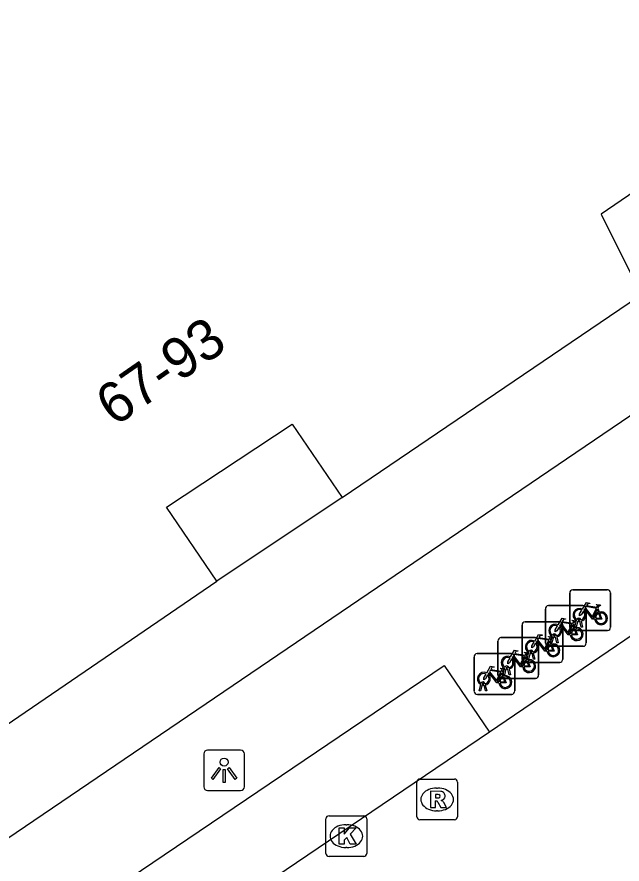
# Model space of a CAD drawing. Extents: x 160037 to 160839, y 385326 to 386441.
# Drawn here: x 160304.54 to 160319.39, y 386009.62 to 386030.43 of the extents above; entities that cross this region are included whole.
import ezdxf

# ---------------------------------------------------------------- set-up
doc = ezdxf.new("R2010")
doc.units = 0
for name, color, linetype in [('IMGEO_Fietsenrek', 7, 'Continuous'), ('IMGEO_Kolk', 7, 'Continuous'), ('IMGEO_Lichtpunt', 7, 'Continuous'), ('IMGEO_Pand', 7, 'Continuous'), ('IMGEO_Pand_nummerreeks', 7, 'Continuous'), ('IMGEO_Rijbaan_lokaal_open', 7, 'Continuous'), ('IMGEO_Rioolput', 7, 'Continuous'), ('IMGEO_Voetpad_open', 7, 'Continuous')]:
    doc.layers.add(name, color=color, linetype=linetype)

msp = doc.modelspace()

# ---------------------------------------------------------------- linework, layer by layer
at = {"layer": 'IMGEO_Fietsenrek'}
for p, q in [((160318.109, 386015.434), (160318.109, 386016.275)), ((160318.109, 386016.275), (160318.109, 386015.434)), ((160318.184, 386016.359), (160319.025, 386016.359)), ((160319.025, 386016.359), (160318.184, 386016.359)), ((160319.109, 386016.284), (160319.109, 386015.443)), ((160319.109, 386015.443), (160319.109, 386016.284)), ((160317.512, 386015.046), (160317.512, 386015.887)), ((160317.512, 386015.887), (160317.512, 386015.046)), ((160317.587, 386015.971), (160318.428, 386015.971)), ((160318.428, 386015.971), (160317.587, 386015.971)), ((160318.512, 386015.896), (160318.512, 386015.055)), ((160318.512, 386015.055), (160318.512, 386015.896)), ((160318.796, 386015.908), (160318.832, 386015.813)), ((160316.938, 386014.649), (160316.938, 386015.49)), ((160316.938, 386015.49), (160316.938, 386014.649)), ((160317.013, 386015.574), (160317.854, 386015.574)), ((160317.854, 386015.574), (160317.013, 386015.574)), ((160317.938, 386015.499), (160317.938, 386014.658)), ((160317.938, 386014.658), (160317.938, 386015.499)), ((160318.199, 386015.52), (160318.235, 386015.425)), ((160318.236, 386015.443), (160318.275, 386015.603)), ((160318.27, 386015.443), (160318.236, 386015.443)), ((160318.305, 386015.591), (160318.27, 386015.443)), ((160318.347, 386015.615), (160318.346, 386015.619)), ((160318.388, 386015.443), (160318.354, 386015.585)), ((160318.378, 386015.626), (160318.379, 386015.619)), ((160318.386, 386015.589), (160318.421, 386015.443)), ((160318.421, 386015.443), (160318.388, 386015.443)), ((160317.75, 386015.227), (160317.749, 386015.231)), ((160317.781, 386015.238), (160317.782, 386015.231)), ((160319.034, 386015.359), (160318.193, 386015.359)), ((160318.193, 386015.359), (160319.034, 386015.359)), ((160316.345, 386014.26), (160316.345, 386015.101)), ((160316.345, 386015.101), (160316.345, 386014.26)), ((160316.42, 386015.185), (160317.261, 386015.185)), ((160317.261, 386015.185), (160316.42, 386015.185)), ((160317.345, 386015.11), (160317.345, 386014.269)), ((160317.345, 386014.269), (160317.345, 386015.11)), ((160317.625, 386015.123), (160317.661, 386015.028)), ((160317.639, 386015.055), (160317.678, 386015.215)), ((160317.673, 386015.055), (160317.639, 386015.055)), ((160317.708, 386015.203), (160317.673, 386015.055)), ((160317.791, 386015.055), (160317.757, 386015.197)), ((160317.789, 386015.201), (160317.824, 386015.055)), ((160317.824, 386015.055), (160317.791, 386015.055)), ((160317.065, 386014.658), (160317.104, 386014.818)), ((160317.134, 386014.806), (160317.099, 386014.658)), ((160317.176, 386014.83), (160317.175, 386014.834)), ((160317.217, 386014.658), (160317.183, 386014.8)), ((160317.207, 386014.841), (160317.208, 386014.834)), ((160317.215, 386014.804), (160317.25, 386014.658)), ((160318.437, 386014.971), (160317.596, 386014.971)), ((160317.596, 386014.971), (160318.437, 386014.971)), ((160315.76, 386013.866), (160315.76, 386014.707)), ((160315.76, 386014.707), (160315.76, 386013.866)), ((160315.835, 386014.791), (160316.676, 386014.791)), ((160316.676, 386014.791), (160315.835, 386014.791)), ((160316.76, 386014.716), (160316.76, 386013.875)), ((160316.76, 386013.875), (160316.76, 386014.716)), ((160317.032, 386014.734), (160317.068, 386014.639)), ((160317.099, 386014.658), (160317.065, 386014.658)), ((160317.25, 386014.658), (160317.217, 386014.658)), ((160316.472, 386014.269), (160316.511, 386014.429)), ((160316.541, 386014.417), (160316.506, 386014.269)), ((160316.583, 386014.441), (160316.582, 386014.445)), ((160316.624, 386014.269), (160316.59, 386014.411)), ((160316.614, 386014.452), (160316.615, 386014.445)), ((160316.622, 386014.415), (160316.657, 386014.269)), ((160317.863, 386014.574), (160317.022, 386014.574)), ((160317.022, 386014.574), (160317.863, 386014.574)), ((160317.27, 386014.185), (160316.429, 386014.185)), ((160316.429, 386014.185), (160317.27, 386014.185)), ((160316.447, 386014.34), (160316.483, 386014.245)), ((160316.506, 386014.269), (160316.472, 386014.269)), ((160316.657, 386014.269), (160316.624, 386014.269)), ((160315.887, 386013.875), (160315.926, 386014.035)), ((160315.956, 386014.023), (160315.921, 386013.875)), ((160315.998, 386014.047), (160315.997, 386014.051)), ((160316.039, 386013.875), (160316.005, 386014.017)), ((160316.029, 386014.058), (160316.03, 386014.051)), ((160316.037, 386014.021), (160316.072, 386013.875)), ((160316.685, 386013.791), (160315.844, 386013.791)), ((160315.844, 386013.791), (160316.685, 386013.791)), ((160315.921, 386013.875), (160315.887, 386013.875)), ((160316.072, 386013.875), (160316.039, 386013.875))]:
    msp.add_line(p, q, dxfattribs=at)
for points in [[(160318.422, 386015.885), (160318.517, 386016.049), (160318.603, 386016.035), (160318.605, 386016.026), (160318.549, 386016.015), (160318.522, 386015.97), (160318.778, 386015.929)], [(160318.443, 386015.833), (160318.391, 386015.743), (160318.351, 386015.718), (160318.352, 386015.765), (160318.407, 386015.859)], [(160318.718, 386015.641), (160318.668, 386015.641), (160318.477, 386015.892), (160318.458, 386015.86)], [(160318.765, 386015.904), (160318.508, 386015.945), (160318.491, 386015.916), (160318.658, 386015.696), (160318.765, 386015.904)], [(160318.813, 386015.806), (160318.783, 386015.883), (160318.674, 386015.665), (160318.717, 386015.665)], [(160318.778, 386015.929), (160318.803, 386015.978), (160318.797, 386015.982), (160318.774, 386015.986), (160318.762, 386015.993), (160318.761, 386015.996), (160318.763, 386016.001), (160318.858, 386015.986), (160318.86, 386015.976), (160318.85, 386015.963), (160318.838, 386015.957), (160318.824, 386015.963), (160318.796, 386015.908)], [(160317.825, 386015.497), (160317.92, 386015.661), (160318.006, 386015.647), (160318.008, 386015.638), (160317.952, 386015.627), (160317.925, 386015.582), (160318.181, 386015.541)], [(160318.747, 386015.665), (160318.867, 386015.664), (160318.823, 386015.778)], [(160318.843, 386015.785), (160318.898, 386015.64), (160318.748, 386015.64)], [(160317.846, 386015.445), (160317.794, 386015.355), (160317.754, 386015.33), (160317.755, 386015.377), (160317.81, 386015.471)], [(160318.121, 386015.253), (160318.071, 386015.253), (160317.88, 386015.504), (160317.861, 386015.472)], [(160318.168, 386015.516), (160317.911, 386015.557), (160317.894, 386015.528), (160318.061, 386015.308), (160318.168, 386015.516)], [(160318.216, 386015.418), (160318.186, 386015.495), (160318.077, 386015.277), (160318.12, 386015.277)], [(160318.181, 386015.541), (160318.206, 386015.59), (160318.2, 386015.594), (160318.177, 386015.598), (160318.165, 386015.605), (160318.164, 386015.608), (160318.166, 386015.613), (160318.261, 386015.598), (160318.263, 386015.588), (160318.253, 386015.575), (160318.241, 386015.569), (160318.227, 386015.575), (160318.199, 386015.52)], [(160317.251, 386015.1), (160317.346, 386015.264), (160317.432, 386015.25), (160317.434, 386015.241), (160317.378, 386015.23), (160317.351, 386015.185), (160317.607, 386015.144)], [(160318.15, 386015.277), (160318.27, 386015.276), (160318.226, 386015.39)], [(160318.246, 386015.397), (160318.301, 386015.252), (160318.151, 386015.252)], [(160317.272, 386015.048), (160317.22, 386014.958), (160317.18, 386014.933), (160317.181, 386014.98), (160317.236, 386015.074)], [(160317.547, 386014.856), (160317.497, 386014.856), (160317.306, 386015.107), (160317.287, 386015.075)], [(160317.594, 386015.119), (160317.337, 386015.16), (160317.32, 386015.131), (160317.487, 386014.911), (160317.594, 386015.119)], [(160317.642, 386015.021), (160317.612, 386015.098), (160317.503, 386014.88), (160317.546, 386014.88)], [(160317.607, 386015.144), (160317.632, 386015.193), (160317.626, 386015.197), (160317.603, 386015.201), (160317.591, 386015.208), (160317.59, 386015.211), (160317.592, 386015.216), (160317.687, 386015.201), (160317.689, 386015.191), (160317.679, 386015.178), (160317.667, 386015.172), (160317.653, 386015.178), (160317.625, 386015.123)], [(160316.658, 386014.711), (160316.753, 386014.875), (160316.839, 386014.861), (160316.841, 386014.852), (160316.785, 386014.841), (160316.758, 386014.796), (160317.014, 386014.755)], [(160317.014, 386014.755), (160317.039, 386014.804), (160317.033, 386014.808), (160317.01, 386014.812), (160316.998, 386014.819), (160316.997, 386014.822), (160316.999, 386014.827), (160317.094, 386014.812), (160317.096, 386014.802), (160317.086, 386014.789), (160317.074, 386014.783), (160317.06, 386014.789), (160317.032, 386014.734)], [(160317.576, 386014.88), (160317.696, 386014.879), (160317.652, 386014.993)], [(160317.672, 386015), (160317.727, 386014.855), (160317.577, 386014.855)], [(160316.679, 386014.659), (160316.627, 386014.569), (160316.587, 386014.544), (160316.588, 386014.591), (160316.643, 386014.685)], [(160316.954, 386014.467), (160316.904, 386014.467), (160316.713, 386014.718), (160316.694, 386014.686)], [(160317.001, 386014.73), (160316.744, 386014.771), (160316.727, 386014.742), (160316.894, 386014.522), (160317.001, 386014.73)], [(160317.049, 386014.632), (160317.019, 386014.709), (160316.91, 386014.491), (160316.953, 386014.491)], [(160316.983, 386014.491), (160317.103, 386014.49), (160317.059, 386014.604)], [(160317.079, 386014.611), (160317.134, 386014.466), (160316.984, 386014.466)], [(160316.073, 386014.317), (160316.168, 386014.481), (160316.254, 386014.467), (160316.256, 386014.458), (160316.2, 386014.447), (160316.173, 386014.402), (160316.429, 386014.361)], [(160316.429, 386014.361), (160316.454, 386014.41), (160316.448, 386014.414), (160316.425, 386014.418), (160316.413, 386014.425), (160316.412, 386014.428), (160316.414, 386014.433), (160316.509, 386014.418), (160316.511, 386014.408), (160316.501, 386014.395), (160316.489, 386014.389), (160316.475, 386014.395), (160316.447, 386014.34)], [(160316.094, 386014.265), (160316.042, 386014.175), (160316.002, 386014.15), (160316.003, 386014.197), (160316.058, 386014.291)], [(160316.369, 386014.073), (160316.319, 386014.073), (160316.128, 386014.324), (160316.109, 386014.292)], [(160316.416, 386014.336), (160316.159, 386014.377), (160316.142, 386014.348), (160316.309, 386014.128), (160316.416, 386014.336)], [(160316.464, 386014.238), (160316.434, 386014.315), (160316.325, 386014.097), (160316.368, 386014.097)], [(160316.398, 386014.097), (160316.518, 386014.096), (160316.474, 386014.21)], [(160316.494, 386014.217), (160316.549, 386014.072), (160316.399, 386014.072)]]:
    msp.add_lwpolyline(points, dxfattribs=at)
for centre, radius, start, end in [((160318.187, 386016.281), 0.0779, 92.4484, 184.2845), ((160318.187, 386016.281), 0.0779, 92.4484, 184.2845), ((160319.031, 386016.281), 0.0779, 2.4484, 94.2845), ((160319.031, 386016.281), 0.0779, 2.4484, 94.2845), ((160317.59, 386015.893), 0.0779, 92.4484, 184.2845), ((160317.59, 386015.893), 0.0779, 92.4484, 184.2845), ((160318.349, 386015.744), 0.159, 62.6766, 242.1369), ((160318.349, 386015.744), 0.129, 63.3192, 238.903), ((160318.349, 386015.744), 0.159, 283.5766, 46.6042), ((160318.434, 386015.893), 0.0779, 2.4484, 94.2845), ((160318.434, 386015.893), 0.0779, 2.4484, 94.2845), ((160318.329, 386015.615), 0.0499, 12.8025, 158.6934), ((160318.329, 386015.615), 0.0174, 12.8025, 163.4502), ((160318.349, 386015.744), 0.129, 283.6043, 43.4302), ((160318.876, 386015.66), 0.159, 113.3408, 178.3217), ((160318.876, 386015.66), 0.159, 187.0065, 105.7708), ((160318.876, 386015.66), 0.129, 113.923, 177.9556), ((160318.876, 386015.66), 0.129, 188.6715, 104.5883), ((160317.016, 386015.496), 0.0779, 92.4484, 184.2845), ((160317.016, 386015.496), 0.0779, 92.4484, 184.2845), ((160317.752, 386015.356), 0.159, 62.6766, 242.1369), ((160317.752, 386015.356), 0.129, 63.3192, 238.903), ((160317.752, 386015.356), 0.129, 283.6043, 43.4302), ((160317.752, 386015.356), 0.159, 283.5766, 46.6042), ((160317.86, 386015.496), 0.0779, 2.4484, 94.2845), ((160317.86, 386015.496), 0.0779, 2.4484, 94.2845), ((160318.187, 386015.437), 0.0779, 182.4484, 274.2845), ((160318.187, 386015.437), 0.0779, 182.4484, 274.2845), ((160318.279, 386015.272), 0.159, 187.0065, 105.7708), ((160318.349, 386015.744), 0.159, 253.9967, 271.7867), ((160318.349, 386015.744), 0.129, 253.415, 269.0204), ((160319.031, 386015.437), 0.0779, 272.4484, 4.2845), ((160319.031, 386015.437), 0.0779, 272.4484, 4.2845), ((160317.732, 386015.227), 0.0499, 12.8025, 158.6934), ((160317.732, 386015.227), 0.0174, 12.8025, 163.4502), ((160317.752, 386015.356), 0.129, 253.415, 269.0204), ((160318.279, 386015.272), 0.159, 113.3408, 178.3217), ((160318.279, 386015.272), 0.129, 113.923, 177.9556), ((160318.279, 386015.272), 0.129, 188.6715, 104.5883), ((160316.423, 386015.107), 0.0779, 92.4484, 184.2845), ((160316.423, 386015.107), 0.0779, 92.4484, 184.2845), ((160317.178, 386014.959), 0.159, 62.6766, 242.1369), ((160317.178, 386014.959), 0.129, 63.3192, 238.903), ((160317.178, 386014.959), 0.129, 283.6043, 43.4302), ((160317.178, 386014.959), 0.159, 283.5766, 46.6042), ((160317.267, 386015.107), 0.0779, 2.4484, 94.2845), ((160317.267, 386015.107), 0.0779, 2.4484, 94.2845), ((160317.59, 386015.049), 0.0779, 182.4484, 274.2845), ((160317.59, 386015.049), 0.0779, 182.4484, 274.2845), ((160317.705, 386014.875), 0.159, 113.3408, 178.3217), ((160317.705, 386014.875), 0.159, 187.0065, 105.7708), ((160317.752, 386015.356), 0.159, 253.9967, 271.7867), ((160318.434, 386015.049), 0.0779, 272.4484, 4.2845), ((160318.434, 386015.049), 0.0779, 272.4484, 4.2845), ((160317.158, 386014.83), 0.0499, 12.8025, 158.6934), ((160317.178, 386014.959), 0.159, 253.9967, 271.7867), ((160317.158, 386014.83), 0.0174, 12.8025, 163.4502), ((160317.178, 386014.959), 0.129, 253.415, 269.0204), ((160317.705, 386014.875), 0.129, 113.923, 177.9556), ((160317.705, 386014.875), 0.129, 188.6715, 104.5883), ((160315.838, 386014.713), 0.0779, 92.4484, 184.2845), ((160315.838, 386014.713), 0.0779, 92.4484, 184.2845), ((160316.585, 386014.57), 0.159, 62.6766, 242.1369), ((160316.585, 386014.57), 0.129, 63.3192, 238.903), ((160316.585, 386014.57), 0.129, 283.6043, 43.4302), ((160316.585, 386014.57), 0.159, 283.5766, 46.6042), ((160316.682, 386014.713), 0.0779, 2.4484, 94.2845), ((160316.682, 386014.713), 0.0779, 2.4484, 94.2845), ((160317.016, 386014.652), 0.0779, 182.4484, 274.2845), ((160317.016, 386014.652), 0.0779, 182.4484, 274.2845), ((160317.112, 386014.486), 0.159, 113.3408, 178.3217), ((160317.112, 386014.486), 0.159, 187.0065, 105.7708), ((160317.112, 386014.486), 0.129, 113.923, 177.9556), ((160317.112, 386014.486), 0.129, 188.6715, 104.5883), ((160317.86, 386014.652), 0.0779, 272.4484, 4.2845), ((160317.86, 386014.652), 0.0779, 272.4484, 4.2845), ((160316.565, 386014.441), 0.0499, 12.8025, 158.6934), ((160316.585, 386014.57), 0.159, 253.9967, 271.7867), ((160316.565, 386014.441), 0.0174, 12.8025, 163.4502), ((160316.585, 386014.57), 0.129, 253.415, 269.0204), ((160316, 386014.176), 0.159, 62.6766, 242.1369), ((160316, 386014.176), 0.129, 63.3192, 238.903), ((160316, 386014.176), 0.129, 283.6043, 43.4302), ((160316, 386014.176), 0.159, 283.5766, 46.6042), ((160316.423, 386014.263), 0.0779, 182.4484, 274.2845), ((160316.423, 386014.263), 0.0779, 182.4484, 274.2845), ((160316.527, 386014.092), 0.159, 113.3408, 178.3217), ((160316.527, 386014.092), 0.159, 187.0065, 105.7708), ((160316.527, 386014.092), 0.129, 113.923, 177.9556), ((160316.527, 386014.092), 0.129, 188.6715, 104.5883), ((160317.267, 386014.263), 0.0779, 272.4484, 4.2845), ((160317.267, 386014.263), 0.0779, 272.4484, 4.2845), ((160315.98, 386014.047), 0.0499, 12.8025, 158.6934), ((160316, 386014.176), 0.159, 253.9967, 271.7867), ((160315.98, 386014.047), 0.0174, 12.8025, 163.4502), ((160316, 386014.176), 0.129, 253.415, 269.0204), ((160315.838, 386013.869), 0.0779, 182.4484, 274.2845), ((160315.838, 386013.869), 0.0779, 182.4484, 274.2845), ((160316.682, 386013.869), 0.0779, 272.4484, 4.2845), ((160316.682, 386013.869), 0.0779, 272.4484, 4.2845)]:
    msp.add_arc(centre, radius, start, end, dxfattribs=at)
at = {"layer": 'IMGEO_Kolk'}
for p, q in [((160312.126, 386009.884), (160312.126, 386010.736)), ((160312.201, 386010.81), (160313.053, 386010.81)), ((160313.127, 386010.736), (160313.127, 386009.884)), ((160312.614, 386010.59), (160312.639, 386010.59)), ((160312.637, 386010.03), (160312.612, 386010.03)), ((160313.053, 386009.81), (160312.201, 386009.81))]:
    msp.add_line(p, q, dxfattribs=at)
for points in [[(160312.126, 386009.884), (160312.126, 386010.736)], [(160312.201, 386010.81), (160313.053, 386010.81)], [(160313.127, 386010.736), (160313.127, 386009.884)], [(160312.447, 386010.51), (160312.57, 386010.51), (160312.57, 386010.359), (160312.7, 386010.51), (160312.864, 386010.51), (160312.718, 386010.359), (160312.871, 386010.11), (160312.719, 386010.11), (160312.634, 386010.274), (160312.57, 386010.207), (160312.57, 386010.11), (160312.447, 386010.11), (160312.447, 386010.51)], [(160313.053, 386009.81), (160312.201, 386009.81)]]:
    msp.add_lwpolyline(points, dxfattribs=at)
for centre, start, end in [((160312.203, 386010.734), 91.552, 178.448), ((160312.203, 386010.734), 91.552, 178.448), ((160313.051, 386010.734), 1.552, 88.448), ((160313.051, 386010.734), 1.552, 88.448), ((160312.203, 386009.886), 181.552, 268.448), ((160312.203, 386009.886), 181.552, 268.448), ((160313.051, 386009.886), 271.552, 358.448), ((160313.051, 386009.886), 271.552, 358.448)]:
    msp.add_arc(centre, 0.0765, start, end, dxfattribs=at)
for centre, major_axis, ratio, start_param, end_param in [((160312.613, 386010.31), (-0.387, 0.002), 0.722429, 4.712389, 7.853982), ((160312.638, 386010.31), (-0.39, 0.002), 0.717154, 1.570796, 4.712389)]:
    msp.add_ellipse(centre, major_axis=major_axis, ratio=ratio, start_param=start_param, end_param=end_param, dxfattribs=at)
at = {"layer": 'IMGEO_Lichtpunt'}
for p, q in [((160309.127, 386012.329), (160309.127, 386011.522)), ((160309.127, 386012.329), (160309.127, 386011.522)), ((160310.029, 386012.424), (160309.221, 386012.424)), ((160310.029, 386012.424), (160309.221, 386012.424)), ((160310.123, 386011.522), (160310.123, 386012.329)), ((160310.123, 386011.522), (160310.123, 386012.329)), ((160309.221, 386011.428), (160310.029, 386011.428)), ((160309.221, 386011.428), (160310.029, 386011.428))]:
    msp.add_line(p, q, dxfattribs=at)
for points in [[(160309.501, 386011.993), (160309.54, 386011.965), (160309.352, 386011.703), (160309.314, 386011.73), (160309.501, 386011.993)], [(160309.603, 386011.945), (160309.65, 386011.945), (160309.65, 386011.623), (160309.603, 386011.623), (160309.603, 386011.945)], [(160309.713, 386011.965), (160309.751, 386011.992), (160309.938, 386011.73), (160309.899, 386011.702), (160309.713, 386011.965)]]:
    msp.add_lwpolyline(points, dxfattribs=at)
msp.add_circle((160309.626, 386012.127), 0.0994, dxfattribs=at)
for centre, start, end in [((160309.221, 386012.329), 90, 180), ((160309.221, 386012.329), 90, 180), ((160310.029, 386012.329), 0, 90), ((160310.029, 386012.329), 0, 90), ((160309.221, 386011.522), 180, 270), ((160309.221, 386011.522), 180, 270), ((160310.029, 386011.522), 270, 0), ((160310.029, 386011.522), 270, 360)]:
    msp.add_arc(centre, 0.0946, start, end, dxfattribs=at)
at = {"layer": 'IMGEO_Pand'}
for points in [[(160321.617, 386024.801), (160320.375, 386026.606), (160318.884, 386025.58), (160319.86, 386023.609)], [(160312.523, 386018.623), (160319.794, 386023.564), (160319.86, 386023.609)], [(160309.45, 386016.571), (160308.21, 386018.385), (160311.298, 386020.426), (160312.523, 386018.623)], [(160303.18, 386012.291), (160303.287, 386012.365), (160309.45, 386016.571)]]:
    msp.add_lwpolyline(points, dxfattribs=at)
at = {"layer": 'IMGEO_Rijbaan_lokaal_open'}
for points in [[(160321.966, 386016.821), (160316.138, 386012.864)], [(160316.138, 386012.864), (160306.155, 386006.102)]]:
    msp.add_lwpolyline(points, dxfattribs=at)
at = {"layer": 'IMGEO_Rioolput'}
for p, q in [((160314.429, 386011.711), (160315.281, 386011.711)), ((160314.354, 386010.785), (160314.354, 386011.637)), ((160314.842, 386011.491), (160314.867, 386011.491)), ((160315.355, 386011.637), (160315.355, 386010.785)), ((160314.865, 386010.931), (160314.84, 386010.931)), ((160315.281, 386010.711), (160314.429, 386010.711))]:
    msp.add_line(p, q, dxfattribs=at)
for points in [[(160314.429, 386011.711), (160315.281, 386011.711)], [(160314.354, 386010.785), (160314.354, 386011.637)], [(160315.355, 386011.637), (160315.355, 386010.785)], [(160314.943, 386011.409), (160314.691, 386011.411), (160314.691, 386011.011)], [(160314.869, 386011.33), (160314.815, 386011.33), (160314.815, 386011.249)], [(160314.691, 386011.011), (160314.815, 386011.011), (160314.815, 386011.173), (160314.826, 386011.173)], [(160314.815, 386011.249), (160314.867, 386011.249)], [(160314.873, 386011.144), (160314.944, 386011.011), (160315.084, 386011.011), (160315.019, 386011.137)], [(160315.281, 386010.711), (160314.429, 386010.711)]]:
    msp.add_lwpolyline(points, dxfattribs=at)
for centre, radius, start, end in [((160314.431, 386011.635), 0.0765, 91.552, 178.448), ((160314.431, 386011.635), 0.0765, 91.552, 178.448), ((160315.279, 386011.635), 0.0765, 1.552, 88.448), ((160315.279, 386011.635), 0.0765, 1.552, 88.448), ((160314.875, 386011.234), 0.0964, 77.0061, 93.1865), ((160314.889, 386011.291), 0.0378, 276.6634, 79.6772), ((160314.942, 386011.299), 0.109, 350.3612, 89.416), ((160314.94, 386011.299), 0.112, 277.5842, 350.9817), ((160314.825, 386011.12), 0.0533, 26.0293, 88.6989), ((160314.851, 386011.438), 0.19, 274.7715, 282.9687), ((160314.924, 386011.084), 0.108, 29.5134, 73.7905), ((160314.431, 386010.787), 0.0765, 181.552, 268.448), ((160314.431, 386010.787), 0.0765, 181.552, 268.448), ((160315.279, 386010.787), 0.0765, 271.552, 358.448), ((160315.279, 386010.787), 0.0765, 271.552, 358.448)]:
    msp.add_arc(centre, radius, start, end, dxfattribs=at)
for centre, major_axis, ratio, start_param, end_param in [((160314.841, 386011.211), (-0.387, 0.002), 0.722429, 4.712389, 7.853982), ((160314.866, 386011.211), (-0.39, 0.002), 0.717154, 1.570796, 4.712389)]:
    msp.add_ellipse(centre, major_axis=major_axis, ratio=ratio, start_param=start_param, end_param=end_param, dxfattribs=at)
at = {"layer": 'IMGEO_Voetpad_open'}
for points in [[(160343.316, 386039.594), (160344.638, 386037.648), (160289.221, 386000), (160275.764, 385990.858), (160274.499, 385992.721)], [(160312.523, 386018.623), (160309.45, 386016.571)], [(160306.155, 386006.102), (160305.018, 386007.729), (160315.025, 386014.503), (160316.138, 386012.864)]]:
    msp.add_lwpolyline(points, dxfattribs=at)

# ---------------------------------------------------------------- texts
at = {"layer": 'IMGEO_Pand_nummerreeks'}
msp.add_text('67-93', height=1, rotation=34.7384, dxfattribs=at).set_placement((160306.939, 386020.35))

doc.saveas('drawing.dxf')
